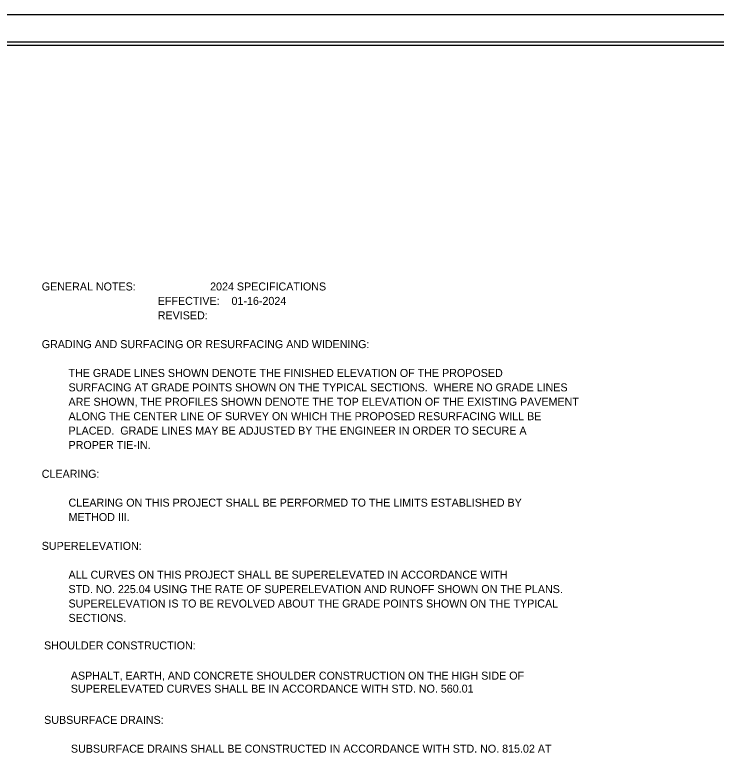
# Model space of a CAD drawing. Extents: x 3312684 to 3314684, y -677777 to -676682.
# Drawn here: x 3313659 to 3314171, y -677225 to -676682 of the extents above; entities that cross this region are included whole.
import ezdxf

# ---------------------------------------------------------------- set-up
doc = ezdxf.new("R2010")
doc.units = 0
for name, color, linetype in [('Default', 7, 'Continuous'), ('Sheet Plan CELL', 7, 'Continuous'), ('Sheet Plot Border Inside CELL', 7, 'Continuous'), ('Sheet Plot Border Outside CELL', 7, 'Continuous')]:
    doc.layers.add(name, color=color, linetype=linetype)

msp = doc.modelspace()

# ---------------------------------------------------------------- linework, layer by layer
at = {"layer": 'Sheet Plan CELL'}
msp.add_lwpolyline([(3314666.73, -676704.55), (3313166.73, -676704.55), (3313166.73, -677754.55), (3314666.73, -677754.55)], close=True, dxfattribs=at)
at = {"layer": 'Sheet Plot Border Inside CELL'}
msp.add_lwpolyline([(3313013.23, -677757.05), (3314679.23, -677757.05), (3314679.23, -676702.05), (3313013.23, -676702.05)], close=True, dxfattribs=at)
at = {"layer": 'Sheet Plot Border Outside CELL'}
msp.add_lwpolyline([(3313000.23, -677777.05), (3314683.73, -677777.05), (3314683.73, -676682.05), (3313000.23, -676682.05)], close=True, dxfattribs=at)

# ---------------------------------------------------------------- texts
at = {"layer": 'Default'}
for s, p in [('GENERAL NOTES:                         2024 SPECIFICATIONS', (3313678.66, -676883.44)), ('                                       EFFECTIVE:    01-16-2024', (3313678.66, -676893.97)), ('                                       REVISED:      ', (3313678.66, -676904.5)), ('GRADING AND SURFACING OR RESURFACING AND WIDENING:  ', (3313678.66, -676925.56)), ('         THE GRADE LINES SHOWN DENOTE THE FINISHED ELEVATION OF THE PROPOSED ', (3313678.66, -676946.61)), ('         SURFACING AT GRADE POINTS SHOWN ON THE TYPICAL SECTIONS.  WHERE NO GRADE LINES ', (3313678.66, -676957.14)), ('         ARE SHOWN, THE PROFILES SHOWN DENOTE THE TOP ELEVATION OF THE EXISTING PAVEMENT ', (3313678.66, -676967.67)), ('         ALONG THE CENTER LINE OF SURVEY ON WHICH THE PROPOSED RESURFACING WILL BE ', (3313678.66, -676978.2)), ('         PLACED.  GRADE LINES MAY BE ADJUSTED BY THE ENGINEER IN ORDER TO SECURE A ', (3313678.66, -676988.73)), ('         PROPER TIE-IN.  ', (3313678.66, -676999.25)), ('CLEARING:  ', (3313678.66, -677020.31)), ('         CLEARING ON THIS PROJECT SHALL BE PERFORMED TO THE LIMITS ESTABLISHED BY ', (3313678.66, -677041.37)), ('         METHOD III.', (3313678.66, -677051.9)), ('SUPERELEVATION:  ', (3313678.66, -677072.95)), ('         ALL CURVES ON THIS PROJECT SHALL BE SUPERELEVATED IN ACCORDANCE WITH', (3313678.66, -677094.01)), ('         STD. NO. 225.04 USING THE RATE OF SUPERELEVATION AND RUNOFF SHOWN ON THE PLANS.', (3313678.66, -677104.54)), ('         SUPERELEVATION IS TO BE REVOLVED ABOUT THE GRADE POINTS SHOWN ON THE TYPICAL ', (3313678.66, -677115.07)), ('         SECTIONS.  ', (3313678.66, -677125.59)), ('SHOULDER CONSTRUCTION:', (3313680.35, -677145.7)), ('         ASPHALT, EARTH, AND CONCRETE SHOULDER CONSTRUCTION ON THE HIGH SIDE OF ', (3313680.35, -677167.79)), ('         SUPERELEVATED CURVES SHALL BE IN ACCORDANCE WITH STD. NO. 560.01', (3313680.35, -677177.29)), ('SUBSURFACE DRAINS:', (3313680.4, -677200.1)), ('         SUBSURFACE DRAINS SHALL BE CONSTRUCTED IN ACCORDANCE WITH STD. NO. 815.02 AT ', (3313680.4, -677221.15))]:
    msp.add_text(s, height=5.849, dxfattribs=at).set_placement(p)

doc.saveas('drawing.dxf')
